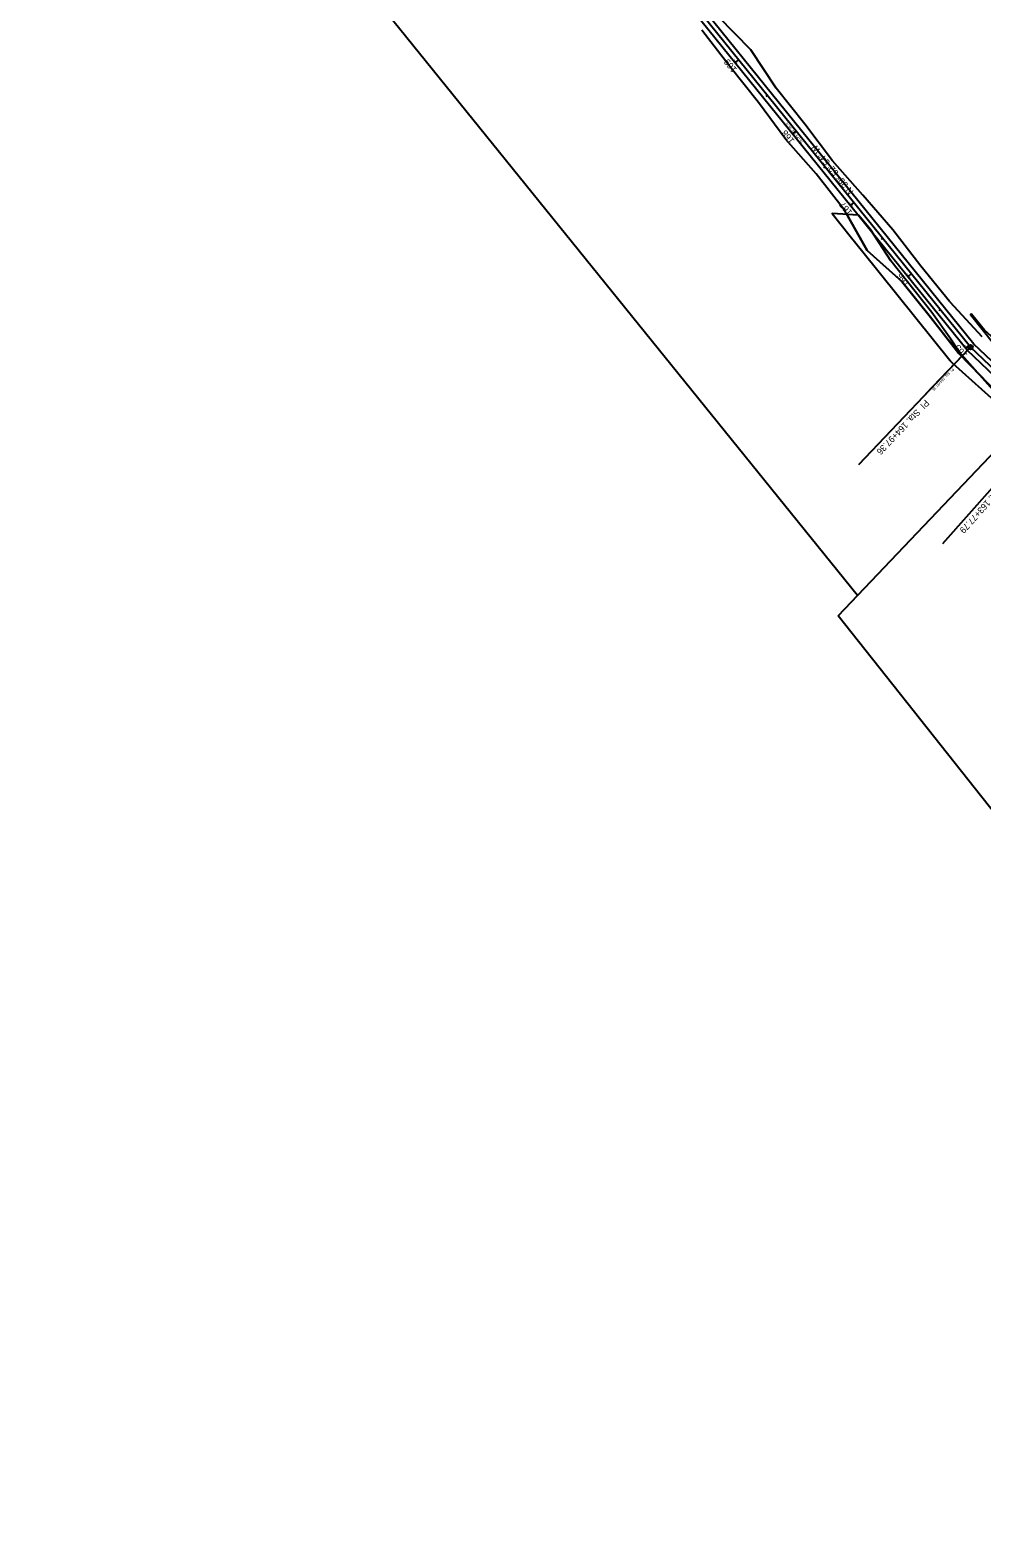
# Model space of a CAD drawing. Extents: x 2399886 to 2513208, y 556821 to 592417.
# Drawn here: x 2435661 to 2436698, y 564864 to 566507 of the extents above; entities that cross this region are included whole.
import ezdxf

# ---------------------------------------------------------------- set-up
doc = ezdxf.new("R2010")
doc.units = 0
for name, color, linetype in [('GM_X_Interchange_Ramps', 7, 'Continuous'), ('GM_X_Major_Lake_Text', 7, 'Continuous'), ('GM_X_Major_River', 7, 'Continuous'), ('GM_X_Major_River_Text', 7, 'Continuous'), ('GM_X_Section', 7, 'Continuous'), ('GM_X_Township', 7, 'Continuous'), ('SH_Data', 7, 'Continuous')]:
    doc.layers.add(name, color=color, linetype=linetype)

msp = doc.modelspace()

# ---------------------------------------------------------------- linework, layer by layer
at = {"layer": 'GM_X_Interchange_Ramps'}
for p, q in [((2436423.3, 566467.5), (2436393, 566507.3)), ((2436454.7, 566428.6), (2436423.3, 566467.5)), ((2436484.3, 566388.2), (2436454.7, 566428.6)), ((2436517.3, 566350.6), (2436484.3, 566388.2)), ((2436548.1, 566311.2), (2436517.3, 566350.6)), ((2436572.9, 566267), (2436548.1, 566311.2)), ((2436610.9, 566233.4), (2436572.9, 566267)), ((2436642.1, 566194.3), (2436610.9, 566233.4)), ((2436663, 566211.2), (2436697.9, 566173.3)), ((2436672.7, 566154.7), (2436642.1, 566194.3)), ((2436709, 566117.7), (2436672.7, 566154.7))]:
    msp.add_line(p, q, dxfattribs=at)
msp.add_lwpolyline([(2436663, 566211.2), (2436631.5, 566250), (2436600.9, 566289.5), (2436568.1, 566327.4), (2436535.1, 566365), (2436504.9, 566404.8), (2436473.8, 566444), (2436446.2, 566486), (2436411.1, 566521.9), (2436379.1, 566559)], dxfattribs=at)
at = {"layer": 'GM_X_Major_Lake_Text'}
for p, q in [((2436550.9, 566306.3), (2436572.9, 566267)), ((2436572.9, 566267), (2436610.9, 566233.4)), ((2436610.9, 566233.4), (2436642.1, 566194.3)), ((2436642.1, 566194.3), (2436672.7, 566154.7)), ((2436664.1, 566170.3), (2436643.3, 566199.5)), ((2436673.3, 566156.6), (2436664.1, 566170.3)), ((2436672.7, 566154.7), (2436696.3, 566130.6)), ((2436696.3, 566130.6), (2436673.3, 566156.6))]:
    msp.add_line(p, q, dxfattribs=at)
for points in [[(2436729.9, 566092.8), (2436673.3, 566156.6), (2436664.1, 566170.3), (2436643.3, 566199.5), (2436598.7, 566255.8), (2436576.6, 566289.9), (2436567.4, 566300.9), (2436563.6, 566305.5), (2436534.9, 566307.4), (2436554.5, 566282.8), (2436568.2, 566265.8), (2436663, 566147.4), (2436663.4, 566146.9), (2436665.8, 566144.4), (2436718.5, 566096.9), (2436732.7, 566084.1), (2436729.9, 566092.8)], [(2436567.4, 566300.9), (2436563.6, 566305.5), (2436550.9, 566306.3)], [(2436643.3, 566199.5), (2436598.7, 566255.8), (2436576.6, 566289.9), (2436567.4, 566300.9)], [(2436891.7, 566007.6), (2436889.2, 566010.3), (2436700.8, 566180.2), (2436686.7, 566197.8), (2436685.4, 566197.3), (2436712.3, 566163.6), (2436784.4, 566090.2), (2436856.6, 566031.4), (2436887.8, 566004.1), (2436911.5, 565983.3), (2436891.7, 566007.6)]]:
    msp.add_lwpolyline(points, dxfattribs=at)
at = {"layer": 'GM_X_Major_River'}
for p, q in [((2436685.5, 566161.7), (2436309, 566628.5)), ((2436432.7, 566475.1), (2436428.8, 566471.9)), ((2436495.5, 566397.2), (2436491.6, 566394.1)), ((2436558.3, 566319.4), (2436554.4, 566316.3)), ((2436621, 566241.6), (2436617.1, 566238.4)), ((2436683.7, 566159.8), (2436563.6, 566033.6)), ((2436683.8, 566163.7), (2436679.9, 566160.6)), ((2436772.1, 566079.2), (2436685.5, 566161.7)), ((2436770.4, 566077.4), (2436654.9, 565947.4))]:
    msp.add_line(p, q, dxfattribs=at)
msp.add_circle((2436685.5, 566161.7), 2.5, dxfattribs=at)
at = {"layer": 'GM_X_Major_River_Text'}
for p, q in [((2436562.3, 565891), (2435661.1, 567007.2)), ((2436541.2, 565868.9), (2436921.3, 566268.2)), ((2437337.2, 564863.7), (2436541.2, 565868.9))]:
    msp.add_line(p, q, dxfattribs=at)
at = {"layer": 'GM_X_Section'}
for p, q in [((2436689.1, 566165.1), (2436312.9, 566631.6)), ((2436681.8, 566158.3), (2436305.1, 566625.3)), ((2436768.7, 566075.5), (2436681.8, 566158.3)), ((2436775.5, 566082.9), (2436689.1, 566165.1))]:
    msp.add_line(p, q, dxfattribs=at)
at = {"layer": 'GM_X_Township'}
for p, q in [((2436685.5, 566161.7), (2436309, 566628.5)), ((2436685.4, 566161.6), (2436685.5, 566161.7)), ((2436685.4, 566161.7), (2436685.5, 566161.6)), ((2436772.1, 566079.2), (2436685.5, 566161.7))]:
    msp.add_line(p, q, dxfattribs=at)
at = {"layer": 'SH_Data'}
for p, q in [((2436685.5, 566161.7), (2436309, 566628.5)), ((2436432.7, 566475.1), (2436431.2, 566473.8)), ((2436464.1, 566436.2), (2436462.5, 566434.9)), ((2436495.5, 566397.2), (2436493.9, 566396)), ((2436526.9, 566358.3), (2436525.3, 566357.1)), ((2436558.3, 566319.4), (2436556.7, 566318.1)), ((2436589.6, 566280.5), (2436588.1, 566279.2)), ((2436621, 566241.6), (2436619.5, 566240.3)), ((2436652.4, 566202.6), (2436650.9, 566201.4)), ((2436684.8, 566160.9), (2436636.7, 566110.4)), ((2436683.8, 566163.7), (2436682.2, 566162.5)), ((2436772.1, 566079.2), (2436685.5, 566161.7))]:
    msp.add_line(p, q, dxfattribs=at)
msp.add_circle((2436685.5, 566161.7), 1, dxfattribs=at)

# ---------------------------------------------------------------- texts
at = {"layer": 'GM_X_Major_River'}
for s, rotation, p in [('169', 128.8816, (2436431.5, 566464.6)), ('168', 128.8816, (2436494.2, 566386.9)), ('N 38%%d 52\' 54" W', 128.8816, (2436558.6, 566331.6)), ('167', 128.8816, (2436557.2, 566308.8)), ('166', 128.8816, (2436619.9, 566231.1)), ('165', 128.8816, (2436682.6, 566153.2)), ('PI  Sta. 164+97.36', 226.4164, (2436636.3, 566104.9)), ('PI  Sta. 163+77.79', 228.3629, (2436724.9, 566020.8))]:
    msp.add_text(s, height=7, rotation=rotation, dxfattribs=at).set_placement(p)
at = {"layer": 'GM_X_Township'}
msp.add_text('TEMP65', height=0.14, dxfattribs=at).set_placement((2436684.7, 566161.7))
at = {"layer": 'SH_Data'}
for s, rotation, p in [('169', 128.8816, (2436432.2, 566470.9)), ('N 38%%d 52\' 54" W', 308.8816, (2436483.7, 566405.1)), ('168', 128.8816, (2436495, 566393.1)), ('167', 128.8816, (2436557.8, 566315.2)), ('166', 128.8816, (2436620.6, 566237.4)), ('165', 128.8816, (2436683.3, 566159.5)), ('PI  Sta. 164+97.36', 226.4164, (2436665.8, 566139))]:
    msp.add_text(s, height=2.8, rotation=rotation, dxfattribs=at).set_placement(p)

doc.saveas('drawing.dxf')
